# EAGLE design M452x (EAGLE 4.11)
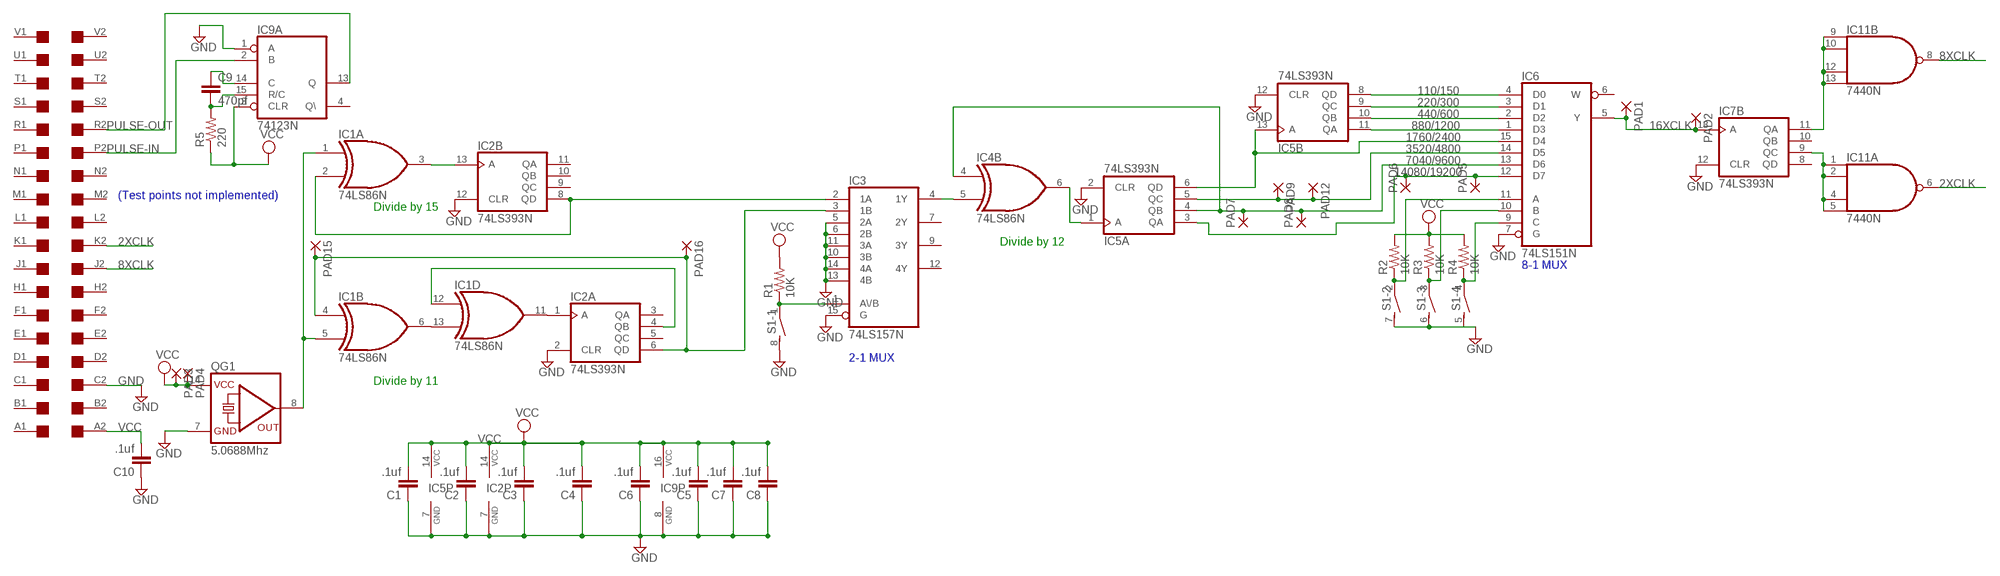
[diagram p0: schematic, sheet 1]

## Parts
C1  .1uf  C-EU050-025X075  [C050-025X075]
C2  .1uf  C-EU050-025X075  [C050-025X075]
C3  .1uf  C-EU050-025X075  [C050-025X075]
C4  .1uf  C-EU050-025X075  [C050-025X075]
C5  .1uf  C-EU050-025X075  [C050-025X075]
C6  .1uf  C-EU050-025X075  [C050-025X075]
C7  .1uf  C-EU050-025X075  [C050-025X075]
C8  .1uf  C-EU050-025X075  [C050-025X075]
C9  470pf  C-EU050-025X075  [C050-025X075]
C10  .1uf  C-EU050-025X075  [C050-025X075]
IC1  74LS86N  [DIL14]
IC2  74LS393N  [DIL14]
IC3  74LS157N  [DIL16]
IC4  74LS86N  [DIL14]
IC5  74LS393N  [DIL14]
IC6  74LS151N  74151N  [DIL16]
IC7  74LS393N  [DIL14]
IC9  74123N  [DIL16]
IC11  7440N  74S20N  [DIL14]
PAD1  1,6/0,8  [1,6/0,8]
PAD2  1,6/0,8  [1,6/0,8]
PAD3  1,6/0,8  [1,6/0,8]
PAD4  1,6/0,8  [1,6/0,8]
PAD5  1,6/0,8  [1,6/0,8]
PAD6  1,6/0,8  [1,6/0,8]
PAD7  1,6/0,8  [1,6/0,8]
PAD8  1,6/0,8  [1,6/0,8]
PAD9  1,6/0,8  [1,6/0,8]
PAD12  1,6/0,8  [1,6/0,8]
PAD15  1,6/0,8  [1,6/0,8]
PAD16  1,6/0,8  [1,6/0,8]
QG1  5.0688Mhz  QG5860  [DIL14S]
R1  10K  R-US_0204/7  [0204/7]
R2  10K  R-US_0204/7  [0204/7]
R3  10K  R-US_0204/7  [0204/7]
R4  10K  R-US_0204/7  [0204/7]
R5  220  R-US_0204/7  [0204/7]
S1  DIP04S  [DIP04S]
U$1  DEC-FLIPCHIP  [DEC-FLIPCHIP]

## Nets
2XCLK: IC11.6(A:O) U$1.K2
8XCLK: IC11.8(B:O) U$1.J2
16XCLK: IC6.5(Y) IC7.13(B:A) PAD1.1(P) PAD2.1(P)
110/150: IC5.8(B:QD) IC6.4(D0)
220/300: IC5.9(B:QC) IC6.3(D1)
440/600: IC5.10(B:QB) IC6.2(D2)
880/1200: IC5.11(B:QA) IC6.1(D3)
1760/2400: IC5.6(A:QD) IC5.13(B:A) IC6.15(D4)
3520/4800: IC5.5(A:QC) IC6.14(D5) PAD9.1(P) PAD12.1(P)
7040/9600: IC4.4(B:I0) IC5.4(A:QB) IC6.13(D6) PAD7.1(P) PAD8.1(P)
14080/19200: IC5.3(A:QA) IC6.12(D7) PAD5.1(P) PAD6.1(P)
GND: C1.1 C2.1 C3.1 C4.1 C5.1 C6.1 C7.1 C8.1 C10.1 IC2.2(A:CLR) IC2.7(P:GND) IC2.12(B:CLR) IC3.5(2A) IC3.6(2B) IC3.10(3B) IC3.11(3A) IC3.13(4B) IC3.14(4A) IC3.15(G) IC5.2(A:CLR) IC5.7(P:GND) IC5.12(B:CLR) IC6.7(G) IC7.12(B:CLR) IC9.1(A:A) IC9.8(P:GND) QG1.7(GND) S1.5 S1.6 S1.7 S1.8 U$1.C2
N$1: IC1.1(A:I0) IC1.5(B:I1) QG1.8(OUT)
N$2: IC1.2(A:I1) IC2.8(B:QD) IC3.2(1A)
N$3: IC1.4(B:I0) IC2.6(A:QD) IC3.3(1B) PAD15.1(P) PAD16.1(P)
N$6: IC1.3(A:O) IC2.13(B:A)
N$7: IC1.11(D:O) IC2.1(A:A)
N$8: IC6.11(A) R2.1 S1.2
N$9: IC3.4(1Y) IC4.5(B:I1)
N$10: IC7.9(B:QC) IC11.1(A:I0) IC11.2(A:I1) IC11.4(A:I2) IC11.5(A:I3)
N$11: IC4.6(B:O) IC5.1(A:A)
N$12: IC7.11(B:QA) IC11.9(B:I0) IC11.10(B:I1) IC11.12(B:I2) IC11.13(B:I3)
N$13: IC6.10(B) R3.1 S1.3
N$14: IC6.9(C) R4.1 S1.4
N$15: IC1.6(B:O) IC1.13(D:I1)
N$17: IC3.1(A\/B) R1.1 S1.1
N$19: IC1.12(D:I0) IC2.4(A:QB)
N$21: C9.2 IC9.15(A:R/C) R5.2
N$22: C9.1 IC9.14(A:C)
PULSE-IN: IC9.2(A:B) U$1.P2
PULSE-OUT: IC9.13(A:Q) U$1.R2
VCC: C1.2 C2.2 C3.2 C4.2 C5.2 C6.2 C7.2 C8.2 C10.2 IC2.14(P:VCC) IC5.14(P:VCC) IC9.3(A:CLR) IC9.16(P:VCC) PAD3.1(P) PAD4.1(P) QG1.14(VCC) R1.2 R2.2 R3.2 R4.2 R5.1 U$1.A2
Unconnected: IC1.8(C:O) IC1.9(C:I0) IC1.10(C:I1) IC2.3(A:QA) IC2.5(A:QC) IC2.9(B:QC) IC2.10(B:QB) IC2.11(B:QA) IC3.7(2Y) IC3.9(3Y) IC3.12(4Y) IC4.1(A:I0) IC4.2(A:I1) IC4.3(A:O) IC4.8(C:O) IC4.9(C:I0) IC4.10(C:I1) IC4.11(D:O) IC4.12(D:I0) IC4.13(D:I1) IC6.6(W) IC7.1(A:A) IC7.2(A:CLR) IC7.3(A:QA) IC7.4(A:QB) IC7.5(A:QC) IC7.6(A:QD) IC7.8(B:QD) IC7.10(B:QB) IC9.4(A:Q\) IC9.5(B:Q) IC9.6(B:C) IC9.7(B:R/C) IC9.9(B:A) IC9.10(B:B) IC9.11(B:CLR) IC9.12(B:Q\) U$1.A1 U$1.B1 U$1.B2 U$1.C1 U$1.D1 U$1.D2 U$1.E1 U$1.E2 U$1.F1 U$1.F2 U$1.H1 U$1.H2 U$1.J1 U$1.K1 U$1.L1 U$1.L2 U$1.M1 U$1.M2 U$1.N1 U$1.N2 U$1.P1 U$1.R1 U$1.S1 U$1.S2 U$1.T1 U$1.T2 U$1.U1 U$1.U2 U$1.V1 U$1.V2

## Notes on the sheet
- (Test points not implemented)
- Divide by 15
- Divide by 12
- 8-1 MUX
- 2-1 MUX
- Divide by 11

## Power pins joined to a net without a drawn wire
GND: IC1.7(P:GND) IC3.8(GND) IC4.7(P:GND) IC6.8(GND) IC7.7(P:GND) IC11.7(P:GND)
VCC: IC1.14(P:VCC) IC3.16(VCC) IC4.14(P:VCC) IC6.16(VCC) IC7.14(P:VCC) IC11.14(P:VCC)

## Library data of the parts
C1-C10 = rcl:C-EU: CAPACITOR, European symbol
IC1 IC4 = 74xx-us:74*86: Quad 2-input EXCLUSIV-OR (XOR) gate
IC2 IC5 IC7 = 74xx-us:74*393: Dual 4-bit decade and binary COUNTER
IC3 = 74xx-us:74*157: Quadruple 2-line to 1-line data SELECTOR/MULTIPLEXER
IC6 = 74xx-us:74*151: Data SELECTOR/MULTIPLEXER
IC9 = 74xx-us:74*123: Retriggerable monostable MULTIVIBRATOR
IC11 = 74xx-us:74*20: Dual 4-input NAND gate
PAD1-PAD9 PAD12 PAD15 PAD16 = wirepad:1,6/0,8: THROUGH-HOLE PAD
QG1 = crystal:QG5860: CRYSTAL RESONATOR
R1-R5 = rcl:R-US_: RESISTOR, American symbol
S1 = switch-dil:DIP04S: DIL/CODE SWITCH
U$1 = con-dec:DEC-FLIPCHIP: DEC Flip-Chip single card fingers

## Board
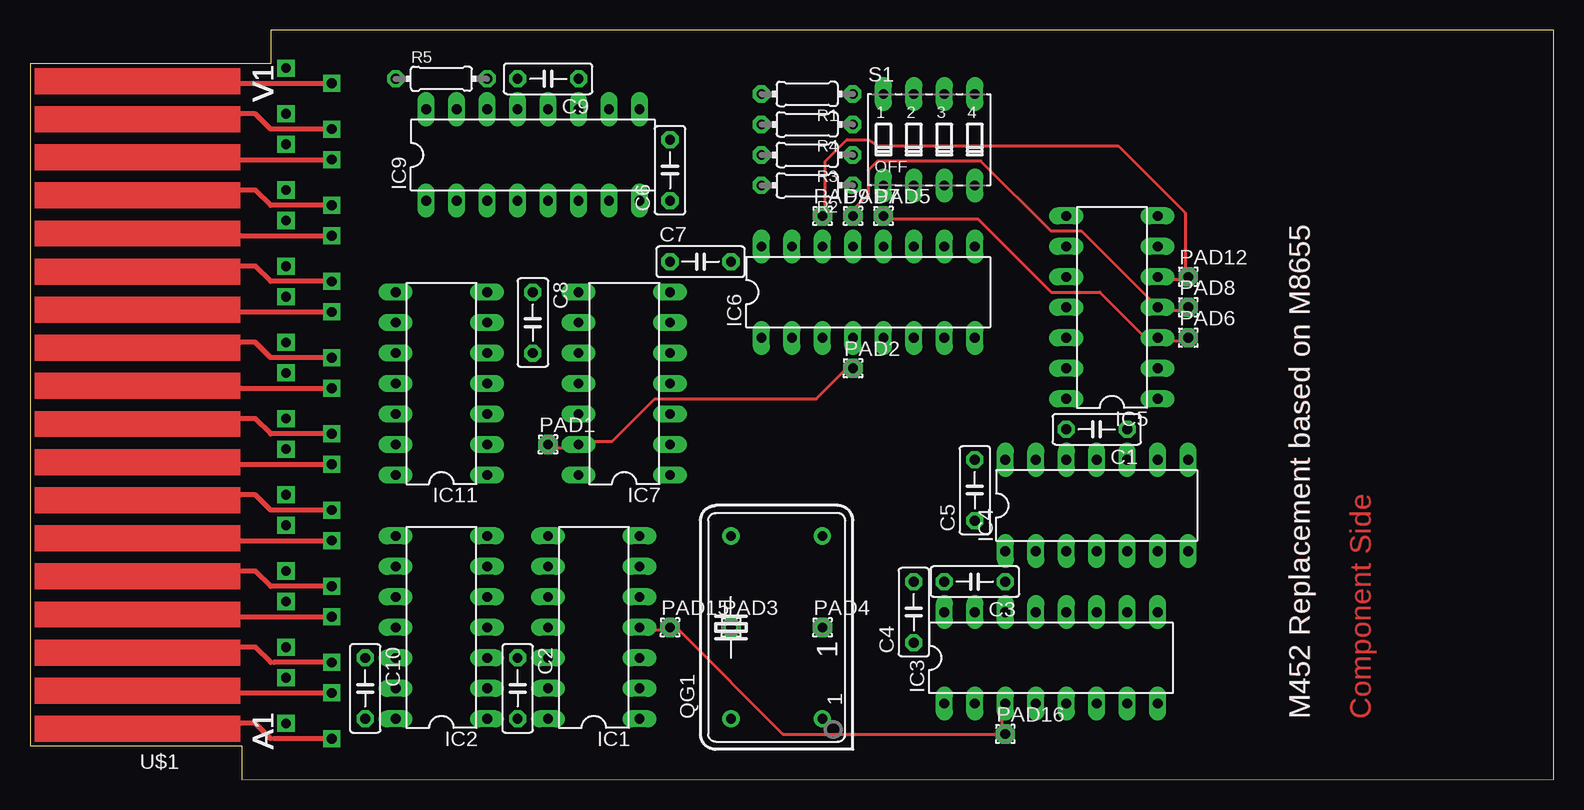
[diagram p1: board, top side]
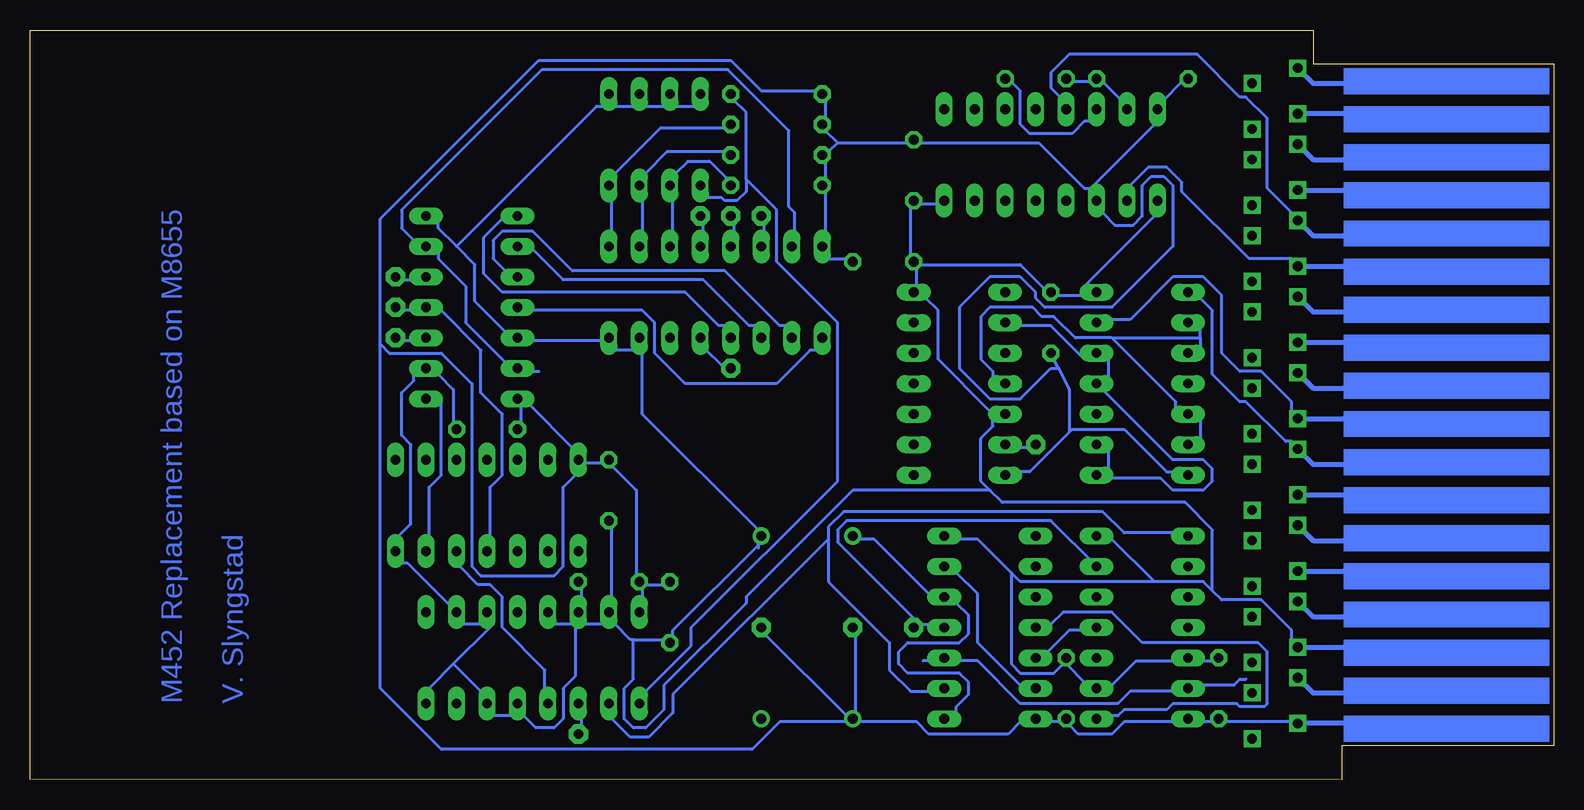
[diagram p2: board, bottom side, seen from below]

Size 126.98 x 62.48 mm. Coordinates in mm from the lower left corner, seen from the top.
Outline: 0,2.83 17.65,2.83 17.65,0 126.98,0.04 126.98,62.45 20.06,62.48 20.06,59.65 0,59.65 0,2.83
Copper layers (1*16): Top 0.035mm / dielectric 1.5mm / Bottom 0.035mm
Design rules "10mils": minimum track width 10mil, minimum drill 28mil, track to track 15mil, track to pad 10mil, pad to pad 10mil, via to via 10mil, smd to smd 10mil, copper to edge 40mil, drill to drill 10mil, minimum pad ring 12mil, minimum via ring 8mil, stop-mask expansion 0mil, vias tented up to drill 0mil, thermal gap 10mil

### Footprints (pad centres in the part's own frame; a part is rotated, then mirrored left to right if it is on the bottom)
C050-025X075 = drill 0.813 octagon: 1 -2.54,0; 2 2.54,0
DIL14 = drill 0.813 long: 1 -7.62,-3.81; 2 -5.08,-3.81; 3 -2.54,-3.81; 4 0,-3.81; 5 2.54,-3.81; 6 5.08,-3.81; 7 7.62,-3.81; 8 7.62,3.81; 9 5.08,3.81; 10 2.54,3.81; 11 0,3.81; 12 -2.54,3.81; 13 -5.08,3.81; 14 -7.62,3.81
DIL16 = drill 0.813 long: 1 -8.89,-3.81; 2 -6.35,-3.81; 3 -3.81,-3.81; 4 -1.27,-3.81; 5 1.27,-3.81; 6 3.81,-3.81; 7 6.35,-3.81; 8 8.89,-3.81; 9 8.89,3.81; 10 6.35,3.81; 11 3.81,3.81; 12 1.27,3.81; 13 -1.27,3.81; 14 -3.81,3.81; 15 -6.35,3.81; 16 -8.89,3.81
1,6/0,8 = drill 0.813 pad 1.6 octagon: 1 0,0
DIL14S = drill 0.813 round: 1 -7.62,-3.81; 7 7.62,-3.81; 8 7.62,3.81; 14 -7.62,3.81
0204/7 = drill 0.813 octagon: 1 -3.81,0; 2 3.81,0
DIP04S = drill 0.813 long: 1 -3.81,-3.81; 2 -1.27,-3.81; 3 1.27,-3.81; 4 3.81,-3.81; 5 3.81,3.81; 6 1.27,3.81; 7 -1.27,3.81; 8 -3.81,3.81
DEC-FLIPCHIP = drill 0.813 square: A1 -7.62,27.94; A2 -3.81,26.67; B1 -7.62,24.13; B2 -3.81,22.86; C1 -7.62,21.59; C2 -3.81,20.32; D1 -7.62,17.78; D2 -3.81,16.51; E1 -7.62,15.24; E2 -3.81,13.97; F1 -7.62,11.43; F2 -3.81,10.16; H1 -7.62,8.89; H2 -3.81,7.62; J1 -7.62,5.08; J2 -3.81,3.81; K1 -7.62,2.54; K2 -3.81,1.27; L1 -7.62,-1.27; L2 -3.81,-2.54; M1 -7.62,-3.81; M2 -3.81,-5.08; N1 -7.62,-7.62; N2 -3.81,-8.89; P1 -7.62,-10.16; P2 -3.81,-11.43; R1 -7.62,-13.97; R2 -3.81,-15.24; S1 -7.62,-16.51; S2 -3.81,-17.78; T1 -7.62,-20.32; T2 -3.81,-21.59; U1 -7.62,-22.86; U2 -3.81,-24.13; V1 -7.62,-26.67; V2 -3.81,-27.94

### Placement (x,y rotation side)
C1  88.9,29.21 180 top
C2  40.63,7.62 270 top
C3  78.73,16.51 180 top
C4  73.66,13.97 90 top
C5  78.73,24.13 90 top
C6  53.34,50.8 90 top
C7  55.88,43.18 0 top
C8  41.9,38.1 270 top
C9  43.17,58.42 180 top
C10  27.94,7.62 270 top
IC1  46.98,12.7 90 top
IC2  34.28,12.7 90 top
IC3  85.09,10.16 0 top
IC4  88.9,22.86 0 top
IC5  90.17,39.37 90 top
IC6  69.84,40.64 0 top
IC7  49.52,33.02 90 top
IC9  41.9,52.07 0 top
IC11  34.28,33.02 90 top
PAD1  43.17,27.94 0 top
PAD2  68.58,34.29 0 top
PAD3  58.41,12.7 0 top
PAD4  66.04,12.7 0 top
PAD5  71.12,46.99 0 top
PAD6  96.52,36.83 0 top
PAD7  68.58,46.99 0 top
PAD8  96.52,39.37 0 top
PAD9  66.04,46.99 0 top
PAD12  96.52,41.91 0 top
PAD15  53.34,12.7 0 top
PAD16  81.28,3.81 0 top
QG1  62.22,12.7 90 top
R1  64.77,57.15 180 top
R2  64.77,49.53 180 top
R3  64.77,52.07 180 top
R4  64.77,54.61 180 top
R5  34.28,58.42 0 top
S1  74.93,53.34 0 top
U$1  17.52,31.37 180 top

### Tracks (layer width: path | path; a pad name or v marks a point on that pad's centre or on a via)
2XCLK
  Bottom 0.254: U$1.K2 21.84,30.73 21.84,31.5 24.38,34.04 26.16,34.04 27.68,35.56 27.68,40.39 29.21,41.91 31.75,41.91 35.3,38.35 36.82,38.35 IC11.6
8XCLK
  Bottom 0.254: U$1.J2 21.84,28.19 22.35,28.19 25.65,31.5 26.16,31.5 28.44,33.78 28.44,39.12 29.46,40.13 IC11.8
16XCLK
  Top 0.254: PAD1.1 43.94,27.69 44.45,27.69 IC7.13 46.98,28.19 48.51,28.19 52.06,31.75 65.53,31.75 67.81,34.04 PAD2.1
  Bottom 0.254: IC7.13 44.45,27.69 43.94,27.69 PAD1.1 | IC6.5 70.61,35.81 69.34,34.54 PAD2.1
110/150
  Bottom 0.254: IC6.4 69.08,37.85 69.59,37.85 72.39,40.64 87.62,40.64 89.15,42.16 89.15,45.21 87.62,46.74 IC5.8
220/300
  Bottom 0.254: IC6.3 66.54,37.85 67.05,37.85 70.86,41.66 82.55,41.66 85.09,44.2 IC5.9
440/600
  Bottom 0.254: IC6.2 64,37.85 64.51,37.85 69.08,42.42 81.78,42.42 85.09,45.72 87.62,45.72 88.39,44.96 88.39,43.43 87.37,42.42 IC5.10
880/1200
  Bottom 0.254: IC6.1 61.46,35.81 61.97,35.81 64.77,33.02 72.39,33.02 74.93,35.56 74.93,38.1 75.94,39.12 85.09,39.12 IC5.11
1760/2400
  Bottom 0.254: IC6.15 63.24,45.72 63.24,47.24 63.75,47.75 63.75,54.1 68.83,59.18 84.32,59.18 96.01,47.5 96.01,45.97 94.99,44.96 IC5.6 92.96,43.94 92.96,43.43 90.67,41.15 90.67,38.1 87.37,34.8 IC5.13 85.09,34.04 84.58,34.04
3520/4800
  Top 0.254: 95.25,41.66 95.75,41.66 PAD12.1 96.26,42.67 96.26,47.24 90.67,52.83 70.61,52.83 69.84,53.34 68.07,53.34 66.29,51.56 66.29,47.75 PAD9.1
  Bottom 0.254: IC6.14 65.78,45.72 65.78,46.23 PAD9.1 | IC5.5 95.25,41.66 95.75,41.66 PAD12.1
7040/9600
  Top 0.254: PAD8.1 95.75,39.12 95.25,39.12 IC5.4 87.62,45.72 85.09,45.72 79.24,51.56 70.61,51.56 69.84,50.8 69.84,48.77 68.83,47.75 PAD7.1
  Bottom 0.254: IC4.4 88.64,20.32 88.64,24.38 87.62,25.4 87.62,30.48 89.4,32.26 89.4,35.81 92.7,39.12 IC5.4 95.25,39.12 95.75,39.12 PAD8.1 | IC6.13 68.32,45.72 68.32,46.23 PAD7.1
14080/19200
  Top 0.254: PAD6.1 95.75,36.58 95.25,36.58 IC5.3 92.7,37.08 89.15,40.64 85.09,40.64 78.99,46.74 71.88,46.74 PAD5.1
  Bottom 0.254: IC6.12 70.86,45.72 70.86,46.23 PAD5.1 | IC5.3 95.25,36.58 95.75,36.58 PAD6.1
GND
  Bottom 0.254: IC9.8 51.3,48.01 52.83,48.01 C6.1 53.59,47.75 53.59,43.69 C7.1 | C7.1 53.08,42.67 53.08,41.15 IC7.7 52.32,40.13 51.3,39.12 51.3,35.05 46.98,30.73 IC7.12 46.73,29.97 46.73,29.46 47.75,28.45 47.75,24.89 46.98,24.13 | C10.1 28.44,9.91 29.21,9.91 IC2.12 31.75,9.91 34.79,9.91 36.82,7.87 IC2.2 39.11,8.13 40.63,9.65 C2.1 40.89,9.65 41.65,8.89 44.45,8.89 45.21,9.65 45.21,17.27 | S1.8 71.62,56.13 73.15,56.13 S1.7 74.16,56.13 75.69,56.13 S1.6 76.7,56.13 78.23,56.13 S1.5 79.24,56.13 79.75,56.13 91.44,44.45 | 91.44,44.45 89.91,42.93 89.91,39.88 87.37,37.34 IC5.12 85.09,36.58 79.24,36.58 IC6.8 78.23,35.81 76.7,35.81 IC6.7 75.94,35.56 75.94,30.48 66.29,20.83 QG1.7 66.29,19.81 66.29,19.56 | 91.44,44.45 92.96,45.97 92.96,46.48 IC5.7 | IC3.14 81.02,15.24 81.02,16 C3.1 | C5.1 78.48,21.08 78.48,15.24 IC3.15 | IC3.14 80.77,12.95 79.24,12.95 IC3.15 | C1.1 91.69,29.72 91.69,32.51 92.96,33.78 IC5.2 94.99,33.78 94.99,33.27 96.01,32.26 96.01,28.7 95.25,27.94 95.25,21.34 96.26,20.32 IC4.7 96.01,18.03 95.5,18.03 IC3.10 90.93,12.95 89.4,12.95 IC3.11 88.64,12.7 91.69,9.65 | 91.69,9.65 93.72,7.62 IC3.8 | 91.69,9.65 89.4,7.37 IC3.6 88.39,5.33 86.86,5.33 IC3.5 85.85,5.33 84.83,4.32 83.31,4.32 82.55,5.08 82.55,7.62 81.53,8.64 81.53,12.7 IC3.14 | IC3.13 83.31,12.95 81.78,12.95 IC3.14 | 76.7,11.68 74.16,11.68 C4.1 73.4,11.94 73.4,12.45 66.29,19.56 | 76.7,11.68 76.96,11.68 78.23,12.95 IC3.15 | 28.44,15.75 29.21,16.51 33.27,16.51 | 28.44,15.75 27.68,14.99 24.38,14.99 21.84,12.45 21.84,11.68 U$1.C2 | 33.27,16.51 36.82,20.07 IC2.7 | 45.21,17.27 44.45,16.51 33.27,16.51
  Bottom 0.254: 45.21,17.27 48,20.07 49.52,20.07 IC1.7 | 46.98,24.13 45.97,23.11 30.73,23.11 28.44,20.83 28.44,15.75 | 46.98,24.13 58.41,24.13 67.31,15.24 67.31,14.73 74.16,7.87 74.16,5.84 75.69,4.32 76.7,4.32 77.47,5.08 77.47,7.62 76.7,8.38 76.7,11.68 | 66.29,19.56 66.29,19.3 | IC11.7 37.08,41.15 | IC11.7 39.36,40.39 41.4,40.39 C8.1 42.41,40.89 44.45,42.93 52.83,42.93 C7.1 | IC9.1 33.27,46.99 39.11,41.15 IC11.7
N$1
  Bottom 0.254: IC1.1 49.78,5.59 49.78,6.1 48.76,7.11 48.76,8.13 49.52,8.89 53.84,8.89 54.6,9.65 54.6,10.67 53.84,11.43 49.52,11.43 48.76,12.19 48.76,13.72 49.78,14.73 IC1.5 52.06,15.49 56.64,20.07 57.91,20.07 QG1.8
N$2
  Bottom 0.254: IC1.2 52.06,7.37 53.59,7.37 55.37,9.14 55.37,11.43 60.45,16.51 60.45,20.07 | 60.45,20.07 60.45,21.08 59.18,22.35 37.59,22.35 35.81,20.57 31.75,20.57 IC2.8 | IC3.2 78.48,5.08 76.96,3.56 75.43,3.56 73.4,5.59 73.4,7.11 60.45,20.07
N$3
  Top 0.254: IC3.3 81.02,5.08 81.02,4.57 PAD16.1 62.73,3.81 54.1,12.45 PAD15.1 52.57,12.45 52.06,12.45 IC1.4
  Bottom 0.254: 52.57,12.95 52.83,12.95 59.68,19.81 59.68,20.83 58.92,21.59 41.9,21.59 IC2.6 | 52.57,12.95 52.06,12.95 IC1.4 | IC3.3 81.02,5.08 81.02,4.57 PAD16.1 | 52.57,12.95 PAD15.1
N$6
  Bottom 0.254: 52.57,9.91 52.06,9.91 IC1.3 49.52,9.91 48,9.91 44.45,6.35 36.32,6.35 35.3,7.37 31.75,7.37 IC2.13 29.21,7.87 26.67,7.87 26.16,8.38 25.65,8.38
N$7
  Bottom 0.254: IC2.1 36.82,5.33 36.32,5.33 35.81,5.84 32.25,5.84 31.75,6.35 26.41,6.35 26.16,6.1 24.12,6.1 23.87,6.35 23.87,10.67 24.63,11.43 34.28,11.43 36.82,13.97 40.89,13.97 41.9,12.95 IC1.11
N$8
  Bottom 0.254: IC6.11 73.4,45.72 73.4,48.26 S1.2 73.15,50.55 72.13,51.56 70.35,51.56 68.83,50.04 R2.1
N$9
  Bottom 0.254: IC3.4 84.07,7.62 84.07,9.14 87.62,12.7 87.62,15.24 88.64,16.26 89.66,16.26 91.18,17.78 IC4.5
N$10
  Bottom 0.254: IC11.2 37.08,27.43 37.08,25.91 IC11.1 36.82,25.15 32.76,25.15 31.75,24.13 29.21,24.13 28.44,24.89 28.44,25.91 29.21,26.67 31.75,26.67 IC11.4 | IC11.4 37.08,33.53 37.08,35.05 IC11.5 | IC11.4 39.11,33.53 | IC11.5 39.11,36.07 | IC7.9 44.45,37.85 41.9,37.85 39.36,35.31 IC11.5
N$11
  Bottom 0.254: IC4.6 93.72,20.32 93.72,24.38 92.7,25.4 92.7,31.5 IC5.1
N$12
  Bottom 0.254: IC7.11 44.45,32.77 | IC11.13 29.46,28.45 29.46,29.97 IC11.12 31.49,30.99 31.49,31.5 36.82,36.83 | 29.46,36.83 29.46,37.59 IC11.9 | 29.46,36.83 29.46,36.07 IC11.10 | 36.82,36.83 29.46,36.83 | IC7.11 46.73,33.53 46.73,34.04 47.75,35.05 47.75,38.61 46.98,39.37 43.43,39.37 42.67,38.61 41.65,38.61 39.87,36.83 36.82,36.83 | IC7.11 44.45,33.27
N$13
  Bottom 0.254: R3.1 69.08,52.32 73.91,52.32 75.69,50.55 S1.3 75.94,48.26 75.94,45.72 IC6.10
N$14
  Bottom 0.254: IC6.9 78.48,45.72 78.48,48.26 S1.4 78.23,50.55 74.42,54.36 69.08,54.36 R4.1
N$15
  Bottom 0.254: IC1.13 44.45,7.87 48,11.43 48,15.49 49.78,17.27 IC1.6
N$17
  Bottom 0.254: 67.31,50.04 67.31,55.63 68.32,56.64 R1.1 | 67.31,50.04 67.31,49.02 68.07,48.26 69.08,48.26 69.34,48.51 70.61,48.51 S1.1 | 67.31,50.04 64.77,47.5 64.77,43.18 59.68,38.1 59.68,24.89 71.88,12.7 71.88,11.18 75.69,7.37 IC3.1
N$19
  Bottom 0.254: IC2.4 39.36,12.45 40.38,12.45 42.16,10.67 IC1.12
N$21
  Bottom 0.254: IC9.15 36.06,56.64 37.59,58.17 R5.2 38.6,58.17 40.13,58.17 C9.2
N$22
  Bottom 0.254: IC9.14 38.6,54.86 39.11,54.86 40.13,53.85 43.68,53.85 44.45,54.61 44.45,57.4 45.21,58.17 C9.1
PULSE-IN
  Bottom 0.254: U$1.P2 21.84,43.43 25.39,43.43 30.98,49.02 30.98,49.78 32.25,51.05 33.78,51.05 35.3,49.53 IC9.2
PULSE-OUT
  Bottom 0.254: U$1.R2 21.84,47.24 23.87,49.28 23.87,55.12 25.65,56.9 26.16,56.9 29.71,60.45 40.38,60.45 41.9,58.93 41.9,57.66 41.14,56.9 IC9.13
VCC
  Bottom 0.254: U$1.A2 21.84,4.83 27.43,4.83 C10.2 28.44,4.83 29.21,4.83 IC2.14 31.75,4.83 35.81,4.83 36.82,3.81 39.62,3.81 40.38,4.57 C2.2 41.14,4.83 41.9,4.83 IC1.14 44.45,4.83 45.46,3.81 52.06,3.81 53.08,4.83 57.91,4.83 QG1.14 | IC3.16 75.94,15.24 75.94,16 C3.2 | C4.2 74.16,16.26 75.69,16.26 C3.2 | IC4.14 80.77,26.42 79.24,26.42 C5.2 78.48,26.16 76.45,24.13 76.45,17.02 C3.2 | C1.2 86.1,29.72 86.1,31.24 IC5.14 85.34,31.24 81.78,27.69 IC4.14 | C7.2 58.92,43.43 60.45,43.43 IC6.16 60.7,45.72 60.7,49.02 R2.2 60.7,50.04 60.7,51.56 R3.2 60.45,52.32 59.68,53.09 | 59.68,53.09 53.84,53.09 C6.2 52.83,53.09 42.92,53.09 39.11,49.28 38.6,49.28 IC9.3 | 59.68,53.09 60.7,54.1 R4.2 60.7,55.12 60.7,56.64 R1.2 61.46,57.4 66.04,57.4 68.58,59.94 84.58,59.94 97.79,46.74 97.79,36.32 | R5.1 30.98,58.17 32.51,56.64 IC9.16 33.27,54.61 38.35,49.53 IC9.3 | 97.79,36.32 97.02,35.56 92.7,35.56 90.17,33.02 90.17,17.78 89.4,17.02 83.31,17.02 82.55,17.78 82.55,24.38 81.53,25.4 IC4.14 | 97.79,36.32 97.79,7.62 92.7,2.54 66.8,2.54 64.51,4.83 58.92,4.83 QG1.14 | 44.45,25.15 IC7.14 44.45,25.65 43.68,25.65 40.38,28.96 | 58.16,11.94 58.16,5.59 QG1.14 | 58.16,11.94 58.16,12.19 | 58.16,11.94 PAD3.1 | QG1.14 58.92,5.33 65.78,12.19 PAD4.1 | 40.38,28.96 40.13,29.21 35.81,29.21 32.25,25.65 31.75,25.65 IC11.14 | 40.38,28.96 40.38,32.51 41.29,34.34 | 41.29,34.34 C8.2 | 41.29,34.34 41.4,34.29 41.9,34.29 44.45,31.75 46.98,31.75 49.52,34.29 49.52,39.37 46.98,41.91 44.45,41.91 43.17,40.64 43.17,40.13 42.41,39.37 36.82,39.37 31.75,44.45 31.75,49.53 32.51,50.29 33.52,50.29 34.28,49.53 34.28,46.99 35.05,46.23 36.57,46.23 37.59,47.24 IC9.3

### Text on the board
Top: M452 Replacement based on M8655 | Component Side
Bottom: V. Slyngstad | M452 Replacement based on M8655
tPlace: 1
tNames: V1 | V1 | V1 | V1 | V1 | V1 | V1 | V1 | V1 | V1 | V1 | V1 | V1 | V1 | V1 | V1 | V1 | V1 | V1 | V1 | V1 | V1 | V1 | V1 | V1 | V1 | V1 | V1 | V1 | V1 | V1 | V1 | M452 Replacement based on M8655 | A1 | A1 | A1 | A1 | A1 | A1 | A1 | A1 | A1 | A1 | A1 | A1 | A1 | A1 | A1 | A1 | A1 | A1 | A1 | A1 | A1 | A1 | A1 | A1 | A1 | A1 | A1 | A1 | A1 | A1 | A1 | A1
_tplace: 470pf | 220 | 10K | 10K | 10K | 74123N | 10K | .1uf | .1uf | .1uf | 74LS151N | 74LS393N | .1uf | 7440N | 74LS393N | 74LS86N | .1uf | .1uf | .1uf | .1uf | 74LS157N | 74LS393N | 74LS86N | 5.0688Mhz
_layer121: 470pf | 470pf | R5 | 220 | 220 | 10K | 10K | S1 | V1 | V1 | V1 | V1 | V1 | V1 | V1 | V1 | V1 | V1 | V1 | V1 | V1 | V1 | V1 | V1 | V1 | V1 | V1 | V1 | V1 | V1 | V1 | V1 | V1 | V1 | V1 | V1 | V1 | V1 | V1 | V1 | C9 | R1 | 10K | 10K | 1 | 2 | 3 | 4 | 10K | 10K | R4 | 74123N | 74123N | R3 | OFF | 10K | 10K | IC9 | PAD9 | R2 | PAD7 | PAD5 | C6 | .1uf | .1uf | C7 | PAD12 | .1uf | .1uf | C8 | .1uf | .1uf | 74LS151N | 74LS151N | PAD8 | IC6 | PAD6 | PAD2 | 74LS393N | 74LS393N | .1uf | .1uf | IC5 | PAD1 | C1 | 7440N | 7440N | 74LS393N | 74LS393N | IC11 | IC7 | 74LS86N | 74LS86N | C5 | .1uf | .1uf | IC4 | .1uf | .1uf | .1uf | C3 | PAD15 | PAD3 | PAD4 | .1uf | .1uf | C10 | .1uf | .1uf | C2 | C4 | 1 | 74LS157N | 74LS157N | IC3 | 74LS393N | 74LS393N | 74LS86N | 74LS86N | 1 | QG1 | 5.0688Mhz | 5.0688Mhz | PAD16 | M452 Replacement based on M8655 | IC2 | IC1 | A1 | A1 | A1 | A1 | A1 | A1 | A1 | A1 | A1 | A1 | A1 | A1 | A1 | A1 | A1 | A1 | A1 | A1 | A1 | A1 | A1 | A1 | A1 | A1 | A1 | A1 | A1 | A1 | A1 | A1 | A1 | A1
